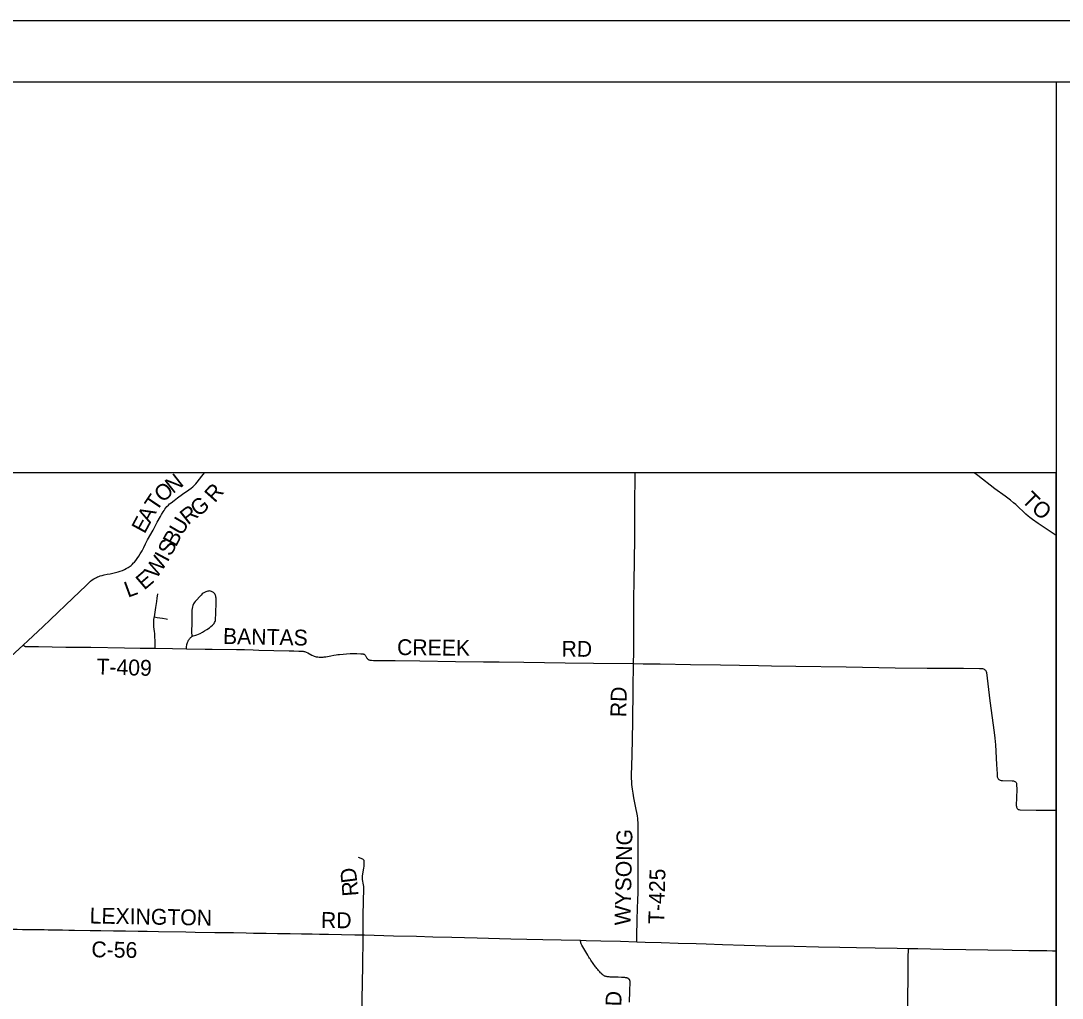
# Model space of a CAD drawing. Extents: x 1341221 to 1914484, y 79347 to 658398.
# Drawn here: x 1397403 to 1435873, y 622283 to 658398 of the extents above; entities that cross this region are included whole.
import ezdxf

# ---------------------------------------------------------------- set-up
doc = ezdxf.new("R2010")
doc.units = 0
for name, color, linetype in [('GM_X_Major_Lake_Text', 7, 'Continuous'), ('GM_X_Major_River_Text', 7, 'Continuous'), ('GM_X_Minor_Lake_Text', 7, 'Continuous'), ('GM_X_Minor_River_Text', 7, 'Continuous'), ('GM_X_Township_Text', 7, 'Continuous'), ('GM_X_US_Shield', 7, 'Continuous')]:
    doc.layers.add(name, color=color, linetype=linetype)

msp = doc.modelspace()

# ---------------------------------------------------------------- linework, layer by layer
at = {"layer": 'GM_X_Minor_Lake_Text'}
msp.add_line((1435649, 656148), (1435649, 561648), dxfattribs=at)
for points in [[(1347971, 656148), (1491971, 656148), (1491971, 561648), (1347971, 561648)], [(1435650, 641695), (1348099, 641695), (1348099, 580425), (1435650, 580425)]]:
    msp.add_lwpolyline(points, close=True, dxfattribs=at)
at = {"layer": 'GM_X_Minor_River_Text'}
msp.add_lwpolyline([(1341221, 559398), (1494221, 559398), (1494221, 658398), (1341221, 658398)], close=True, dxfattribs=at)
at = {"layer": 'GM_X_Township_Text'}
for p, q in [((1407672, 635110), (1407692, 635110)), ((1410047, 624570), (1410046, 624620))]:
    msp.add_line(p, q, dxfattribs=at)
for points in [[(1420038, 634646), (1420043, 635054), (1420050, 635770), (1420053, 637088), (1420061, 637658), (1420082, 639263), (1420092, 640434), (1420102, 641695)], [(1435650, 639377), (1435534, 639450), (1434987, 639822), (1434774, 639971), (1434683, 640039), (1434617, 640096), (1434534, 640171), (1434429, 640270), (1434275, 640415), (1434157, 640522), (1434073, 640592), (1433964, 640680), (1433766, 640832), (1433391, 641110), (1432751, 641598), (1432617, 641695)], [(1402363, 635212), (1402367, 635361), (1402367, 635458), (1402360, 635659), (1402351, 635754), (1402341, 635830), (1402329, 635913), (1402318, 636001), (1402313, 636101), (1402313, 636182), (1402317, 636267), (1402334, 636355), (1402337, 636371), (1402389, 636716), (1402423, 636944), (1402445, 637067), (1402467, 637223)], [(1403524, 635194), (1403526, 635234), (1403529, 635279), (1403535, 635324), (1403540, 635355), (1403550, 635394), (1403559, 635425), (1403572, 635453), (1403586, 635480), (1403603, 635508), (1403621, 635536), (1403640, 635565), (1403657, 635586), (1403677, 635607), (1403694, 635625), (1403726, 635644), (1403772, 635673), (1403821, 635688), (1403864, 635699), (1403907, 635713), (1403967, 635734), (1404025, 635760), (1404109, 635804), (1404192, 635852), (1404277, 635907), (1404369, 635969), (1404428, 636013), (1404489, 636065), (1404520, 636098), (1404544, 636132), (1404564, 636168), (1404577, 636202), (1404589, 636241), (1404597, 636276), (1404601, 636340), (1404605, 636442), (1404615, 636973), (1404614, 637062), (1404610, 637106), (1404605, 637136), (1404596, 637166), (1404582, 637200), (1404566, 637226), (1404546, 637250), (1404524, 637271), (1404499, 637289), (1404473, 637304), (1404444, 637316), (1404415, 637325), (1404384, 637329), (1404354, 637328), (1404317, 637322), (1404281, 637313), (1404234, 637295), (1404183, 637270), (1404140, 637244), (1404105, 637218), (1404062, 637180), (1403842, 636942), (1403808, 636896), (1403784, 636859), (1403770, 636832), (1403754, 636791), (1403741, 636743), (1403731, 636687), (1403726, 636624), (1403723, 636458), (1403720, 636113), (1403711, 635857), (1403709, 635777), (1403715, 635695), (1403726, 635644)], [(1402337, 636371), (1402439, 636355), (1402633, 636325), (1402771, 636301), (1402821, 636290)], [(1397492, 635329), (1397520, 635312), (1397554, 635290), (1397565, 635284), (1397581, 635281), (1398059, 635276), (1399064, 635259), (1399985, 635248), (1401238, 635230), (1401807, 635221), (1402363, 635212), (1403006, 635203), (1403524, 635194), (1404209, 635182), (1404471, 635178), (1405374, 635170), (1405668, 635163), (1405990, 635151), (1406191, 635144), (1406749, 635135), (1407318, 635122), (1407490, 635116), (1407672, 635110)], [(1407692, 635110), (1407772, 635107), (1407802, 635105), (1407830, 635101), (1407857, 635097), (1407881, 635092), (1407919, 635083), (1407950, 635072), (1408003, 635047), (1408151, 634963), (1408210, 634935), (1408243, 634921), (1408276, 634910), (1408309, 634902), (1408343, 634895), (1408381, 634891), (1408419, 634889), (1408471, 634887), (1408519, 634888), (1408567, 634890), (1408612, 634893), (1408676, 634901), (1408850, 634932), (1408964, 634954), (1409055, 634969), (1409119, 634978), (1409177, 634985), (1409306, 634999), (1409440, 635010), (1409566, 635016), (1409687, 635020), (1409771, 635018), (1409810, 635017)], [(1409810, 635017), (1409969, 635011), (1410030, 635008), (1410040, 635007), (1410049, 635005), (1410058, 635003), (1410066, 634999), (1410081, 634991), (1410095, 634982), (1410108, 634973), (1410119, 634962), (1410128, 634952), (1410139, 634937), (1410148, 634919), (1410190, 634850), (1410196, 634842)], [(1410196, 634842), (1410202, 634833), (1410211, 634822), (1410222, 634811), (1410233, 634801), (1410246, 634793), (1410258, 634786), (1410274, 634780), (1410297, 634774), (1410355, 634767), (1410429, 634763), (1411228, 634755), (1412143, 634746), (1413467, 634727), (1414490, 634716), (1415079, 634710), (1415986, 634696), (1417507, 634679), (1418563, 634667), (1420038, 634646), (1420398, 634642), (1421025, 634633), (1422144, 634619), (1423251, 634603), (1424651, 634575), (1425137, 634564), (1426033, 634551), (1427892, 634522), (1429097, 634507), (1429704, 634495), (1430886, 634482), (1432224, 634473), (1432813, 634467), (1432891, 634463), (1432930, 634459), (1432962, 634452), (1432987, 634443), (1433005, 634433), (1433021, 634421), (1433040, 634400), (1433050, 634383), (1433061, 634358), (1433072, 634313), (1433204, 633272), (1433363, 632100), (1433385, 631896), (1433406, 631647), (1433452, 630913), (1433468, 630574), (1433470, 630504), (1433475, 630467), (1433482, 630437), (1433494, 630409), (1433507, 630389), (1433518, 630375), (1433537, 630360), (1433557, 630348), (1433586, 630337), (1433622, 630330), (1433665, 630326), (1434030, 630312), (1434069, 630308), (1434102, 630301), (1434127, 630292), (1434145, 630281), (1434161, 630267), (1434174, 630250), (1434182, 630231), (1434188, 630211), (1434191, 630178), (1434194, 629998), (1434178, 629404), (1434181, 629367), (1434187, 629337), (1434196, 629315), (1434208, 629294), (1434224, 629277), (1434238, 629266), (1434253, 629258), (1434276, 629251), (1434306, 629246), (1434913, 629234), (1435650, 629225)], [(1420163, 624367), (1420163, 624397), (1420163, 624614), (1420168, 625144), (1420181, 625629), (1420192, 625878), (1420204, 626210), (1420207, 626868), (1420211, 627732), (1420208, 628518), (1420206, 628735), (1420205, 628788), (1420202, 628844), (1420195, 628926), (1420182, 629021), (1420113, 629377), (1420050, 629691), (1420020, 629855), (1419998, 630008), (1419979, 630173), (1419971, 630288), (1419967, 630397), (1419968, 630519), (1419982, 631248), (1420008, 632489), (1420027, 633717), (1420038, 634646)], [(1410081, 627370), (1410075, 627384), (1410065, 627396), (1410055, 627406), (1410041, 627415), (1409874, 627485)], [(1410046, 624620), (1410046, 624667), (1410055, 625196), (1410067, 626015), (1410070, 626181), (1410074, 626264), (1410077, 626329), (1410078, 626371), (1410075, 626406), (1410067, 626476), (1410031, 626664), (1410025, 626702), (1410024, 626723), (1410022, 626744), (1410022, 626760), (1410023, 626775), (1410025, 626803), (1410072, 627085), (1410084, 627157), (1410084, 627163), (1410089, 627227), (1410090, 627286), (1410089, 627332), (1410087, 627347), (1410087, 627347), (1410087, 627352), (1410081, 627370)], [(1409929, 616344), (1409934, 616372), (1409936, 616401), (1409939, 616469), (1409941, 616676), (1409945, 617277), (1409955, 618070), (1409962, 618742), (1409971, 619235), (1409985, 620047), (1409998, 620923), (1410005, 621575), (1410016, 622302), (1410025, 622793), (1410037, 623543), (1410048, 624450), (1410047, 624570)], [(1419887, 622141), (1419900, 622537), (1419907, 622695), (1419909, 622745), (1419912, 622794), (1419913, 622819), (1419913, 622838), (1419913, 622856), (1419913, 622871), (1419913, 622885), (1419911, 622899), (1419909, 622910), (1419907, 622920), (1419903, 622932), (1419900, 622941), (1419896, 622951), (1419891, 622961), (1419883, 622972), (1419876, 622981), (1419866, 622991), (1419858, 622998), (1419847, 623005), (1419836, 623012), (1419824, 623018), (1419813, 623023), (1419803, 623027), (1419789, 623031), (1419775, 623035), (1419757, 623038), (1419738, 623040), (1419719, 623041), (1419698, 623043), (1419676, 623043), (1419593, 623047), (1419466, 623053), (1419301, 623059), (1419225, 623063), (1419177, 623065), (1419140, 623068), (1419115, 623070), (1419093, 623072), (1419067, 623076), (1419037, 623080), (1419010, 623086), (1418990, 623092), (1418971, 623098), (1418954, 623107), (1418937, 623117), (1418918, 623130), (1418899, 623144), (1418881, 623159), (1418861, 623179), (1418836, 623204), (1418817, 623225), (1418794, 623252), (1418769, 623281), (1418745, 623310), (1418714, 623346), (1418683, 623385), (1418659, 623414), (1418634, 623445), (1418606, 623481), (1418569, 623530), (1418544, 623565), (1418518, 623601), (1418488, 623645), (1418459, 623690), (1418430, 623737), (1418412, 623764), (1418391, 623799), (1418349, 623868), (1418310, 623932), (1418238, 624053), (1418163, 624180), (1418128, 624243), (1418116, 624265), (1418106, 624286), (1418099, 624302), (1418093, 624317), (1418090, 624331), (1418087, 624348), (1418082, 624392), (1418078, 624423)], [(1418078, 624423), (1418284, 624419), (1418835, 624404), (1419554, 624386), (1420163, 624367)], [(1430084, 613922), (1430084, 613959), (1430092, 614850), (1430100, 615750), (1430106, 616492), (1430114, 617323), (1430124, 617913), (1430132, 618801), (1430139, 619406), (1430150, 620132), (1430158, 620546), (1430158, 620977), (1430162, 621670), (1430168, 622184), (1430179, 623153), (1430184, 623764), (1430191, 624123)]]:
    msp.add_lwpolyline(points, dxfattribs=at)
at = {"layer": 'GM_X_US_Shield'}
for points in [[(1402446, 639874), (1402559, 640083), (1402602, 640156), (1402660, 640251), (1402694, 640306), (1402723, 640349), (1402763, 640402), (1402801, 640447), (1402854, 640500), (1402901, 640545), (1402956, 640592), (1403067, 640679), (1403196, 640775), (1403377, 640904), (1403610, 641064), (1403692, 641126), (1403757, 641179), (1403818, 641236), (1403867, 641288), (1403916, 641347), (1404093, 641578), (1404185, 641695)], [(1401370, 638197), (1401407, 638226), (1401474, 638276), (1401518, 638314), (1401569, 638364), (1401599, 638397), (1401653, 638461), (1401704, 638528), (1401761, 638613), (1401818, 638706), (1401882, 638817), (1401945, 638937), (1402015, 639070), (1402089, 639217), (1402288, 639582), (1402446, 639874)], [(1393736, 631794), (1393893, 631944), (1394127, 632172), (1394288, 632336), (1394529, 632578), (1395031, 633051), (1395480, 633470), (1396285, 634220), (1397196, 635053), (1397492, 635329), (1397678, 635502), (1398215, 636004), (1398503, 636277), (1399323, 637058), (1399817, 637536), (1399903, 637620), (1399983, 637688), (1400042, 637736), (1400096, 637775), (1400155, 637809), (1400194, 637830), (1400233, 637849)], [(1400233, 637849), (1400281, 637868), (1400331, 637885), (1400405, 637906), (1400488, 637924), (1400595, 637948), (1400708, 637968), (1400806, 637989), (1400903, 638012), (1400999, 638039), (1401079, 638065), (1401157, 638092), (1401228, 638121), (1401295, 638155), (1401370, 638197)], [(1396137, 624848), (1396233, 624846), (1396405, 624843), (1396556, 624839), (1396700, 624838), (1396849, 624836), (1397069, 624833), (1397267, 624829), (1397469, 624825)], [(1397469, 624825), (1397665, 624822), (1397813, 624821), (1398013, 624819), (1398262, 624815), (1398411, 624814), (1398575, 624811), (1398940, 624806), (1399183, 624801), (1399391, 624797), (1399970, 624789), (1400353, 624783), (1400827, 624775), (1401275, 624766), (1401736, 624759), (1402075, 624755), (1402491, 624748), (1403502, 624732), (1403847, 624727), (1404570, 624713), (1404826, 624709), (1405261, 624704), (1405726, 624696), (1405997, 624691), (1406124, 624689), (1406466, 624684), (1406886, 624678), (1407359, 624671), (1407769, 624662), (1408169, 624655), (1408440, 624650), (1408766, 624644), (1409245, 624635), (1409746, 624625), (1410046, 624620)], [(1410046, 624620), (1410083, 624619), (1410094, 624619)], [(1410094, 624619), (1411166, 624591), (1412021, 624568), (1412621, 624552), (1413329, 624534), (1414257, 624510), (1415511, 624480), (1416687, 624455), (1417359, 624438), (1418078, 624423)], [(1418078, 624423), (1418284, 624419), (1418835, 624404), (1419554, 624386), (1420163, 624367)], [(1420163, 624367), (1420470, 624357), (1421063, 624339), (1421688, 624320), (1422354, 624300), (1422722, 624286), (1423328, 624262), (1424131, 624236), (1424922, 624218), (1425975, 624199), (1426869, 624183), (1427659, 624165), (1428279, 624154), (1428965, 624143), (1429778, 624129), (1430191, 624123), (1430538, 624118), (1431482, 624099), (1432314, 624082), (1433123, 624068), (1434022, 624055), (1434638, 624049), (1435306, 624039), (1435514, 624035), (1435641, 624035), (1435650, 624035)]]:
    msp.add_lwpolyline(points, dxfattribs=at)

# ---------------------------------------------------------------- texts
at = {"layer": 'GM_X_Major_Lake_Text'}
for s, rotation, p in [('N', 38.2291, (1403022, 640905)), ('O', 40.7983, (1402638, 640573)), ('T', 56.224, (1402422, 640240)), ('R', 48.2948, (1404569, 640563)), ('G', 38.4664, (1403951, 640049)), ('A', 61.3973, (1402183, 639800)), ('R', 38.6921, (1403576, 639749)), ('E', 61.588, (1401975, 639416)), ('U', 59.8657, (1403355, 639347)), ('B', 61.5382, (1403128, 638928)), ('S', 61.5381, (1402940, 638581)), ('W', 55.5804, (1402408, 637752)), ('I', 61.7945, (1402827, 638370)), ('E', 40.5846, (1401964, 637343)), ('L', 20.0109, (1401356, 637078)), ('LEXINGTON', 358.9277, (1399942, 625045)), ('RD', 359.0128, (1408488, 624882)), ('C-56', 358.9701, (1400006, 623798))]:
    msp.add_text(s, height=585, rotation=rotation, dxfattribs=at).set_placement(p)
at = {"layer": 'GM_X_Major_River_Text'}
for s, rotation, p in [('T', 315.0167, (1434341, 640653)), ('O', 321.386, (1434703, 640296)), ('BANTAS', 358.7942, (1404868, 635375)), ('CREEK', 359.393, (1411300, 634963)), ('RD', 359.5064, (1417375, 634903)), ('T-409', 358.3152, (1400191, 634250)), ('RD', 89.0128, (1419768, 632661)), ('WYSONG', 88.7479, (1419922, 624965)), ('D', 96.9983, (1409835, 626575)), ('T-425', 88.5962, (1421168, 625021)), ('R', 94.5008, (1409876, 626069)), ('RD', 89.0118, (1419580, 621414))]:
    msp.add_text(s, height=585, rotation=rotation, dxfattribs=at).set_placement(p)

doc.saveas('drawing.dxf')
